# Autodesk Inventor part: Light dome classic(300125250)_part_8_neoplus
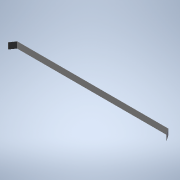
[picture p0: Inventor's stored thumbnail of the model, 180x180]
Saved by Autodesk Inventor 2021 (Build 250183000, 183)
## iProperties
Created: 2026-04
Part Number: Light dome classic(300125250)_part_8_neoplus
Material: Generic
Catalog Web Link: www.3dfindit.com
Description: Light dome classic_part_8_neoplus-
Vendor: KINGSPAN
Document SubType Name: Modeling
Designer: psAdmin
Manufacturer: KINGSPAN
Mass: 64.4652 g
Surface Area: 893.233 cm^2
Volume: 64.4652 cm^3
Density: 1 g/cm^3
Appearance: PSOLRGB-255-255-255
Category: PARTsolutions
Company: KINGSPAN
Title: Light dome classic(300125250)_part_8_neoplus
Author: Cadenas PARTsolutions
PSOL_IDENT_0: {$CADENAS_DATA/23d-libs/kingspan_kla/light_dome_classic_neoplus/parts/part_8.prj},268 {VTYP=3D},{NB=
PSOL_IDENT_1: Light dome classic(300125250)_part_8_neoplus},{LINA=Light dome classic(300125250)_part_8_neoplus},{N
PSOL_IDENT_2: N=Light dome classic_part_8_neoplus},{DATE=15.07.2024 10:56:16},{GEOMDATE=27.09.2022 13:43:52},{VERS
PSOL_IDENT_3: ION=},{LINEID=10},{WBVAR=LODLEVEL,L,W},{WBNUMERIC=W}  {NB=Light dome classic(300125250)_part_8_neopl
PSOL_IDENT_4: us},{LINA=Light dome classic(300125250)_part_8_neoplus},{KT=DUMMY},{IDNR=},{PN=Light dome classic},{
PSOL_IDENT_5: LODLEVEL=300},{L=125},{W=250},{WX=125,250,300},{LX=1250},{XWX=2500}
NB: Light dome classic(300125250)_part_8_neoplus
NN: Light dome classic_part_8_neoplus
NBSYN: $PN.($LODLEVEL.$L.$W.)_part_8_neoplus
LINA: Light dome classic(300125250)_part_8_neoplus
CATALOG: Light + Air
PN: Light dome classic
LODLEVEL: 300
L: 125
W: 250
SUPPLIER: KINGSPAN
ARTICLENO: Light dome classic(300125250)_part_8_neoplus
BOMINFO: Light dome classic(300125250)_part_8_neoplus
CREATOR: CADENAS GmbH
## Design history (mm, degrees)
sketch "Sketch_1"
  geometry: L1 (519.907, 293)-(518.076, 293); L2 (518.076, 293)-(494.096, 258.753); L3 (494.096, 258.753)-(-494.096, 258.753); L4 (-494.096, 258.753)-(-518.076, 293); L5 (-518.076, 293)-(-519.907, 293); L6 (-519.907, 293)-(-494.877, 257.253); L7 (-494.877, 257.253)-(494.877, 257.253); L8 (494.877, 257.253)-(519.907, 293)
  constraints: 16 end point
extrude "Extrusion1" join sketch "Sketch_1" stored distance "d0" = 40; taper "d1" = 0 deg
node "IP_8_XY"
node "IP_8_YZ"
node "IP_8_ZX"
node "IP_8_X"
node "IP_8_Y"
node "IP_8_Z"
node "IP_8_Center"
body "Solid1"
other parameters: "d2" = 0
